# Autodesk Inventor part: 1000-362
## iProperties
Created: 2007-03
Part Number: 1000-362
Document SubType Name: Modeling
Designer: Andy Moles
Material: Steel
Mass: 96.0383 g
Surface Area: 89.1798 cm^2
Volume: 12.2342 cm^3
Density: 7.85 g/cm^3
Author: Andy Moles
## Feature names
1. Base1
